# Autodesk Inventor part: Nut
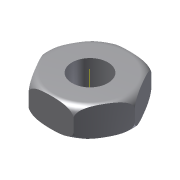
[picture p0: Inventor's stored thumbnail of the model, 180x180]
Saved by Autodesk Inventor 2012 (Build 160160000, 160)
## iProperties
Created: 2009-04
Part Number: Nut
Document SubType Name: Modeling
Designer: Sham
Density: 1 g/cm^3
Material: Default
Author: Sham
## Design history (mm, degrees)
sketch "Sketch1"
  geometry: L1 (7.5, 12.99)-(15, 0); L2 (15, 0)-(7.5, -12.99); L3 (7.5, -12.99)-(-7.5, -12.99); L4 (-7.5, -12.99)-(-15, 0); L5 (-15, 0)-(-7.5, 12.99); L6 (-7.5, 12.99)-(7.5, 12.99); C1 r 6 at (0, 0); 1 further point
  constraints: 12 end point, 1 centre point, 1 coincident, 13 other
  dimensions: "d0" = 30 distance of L1.end L4.end; "d1" = 12 diameter of C1
extrude "Extrusion1" new body sketch "Sketch1" distance "d2" = 12; taper "d3" = 0 deg
sketch "Sketch2"
  geometry: L1 (-12, 0)-(-12, -0.022); L2 (-15, 7)-(-15, 3); L3 (0, -2.87)-(0, 12.87) reference; A1 r 3 centre (-12, 7) between (-12, 10) and (-15, 7); A2 r 3 centre (-12, 3) between (-15, 3) and (-12, 0)
  constraints: 4 end point, 4 point on circle, 2 centre point, 1 tangent
revolve "Revolution1" sketch "Sketch2" stored, may be unused: angle "d7" = 90 deg
body "Solid1"
other parameters: "d6" = 90 deg
